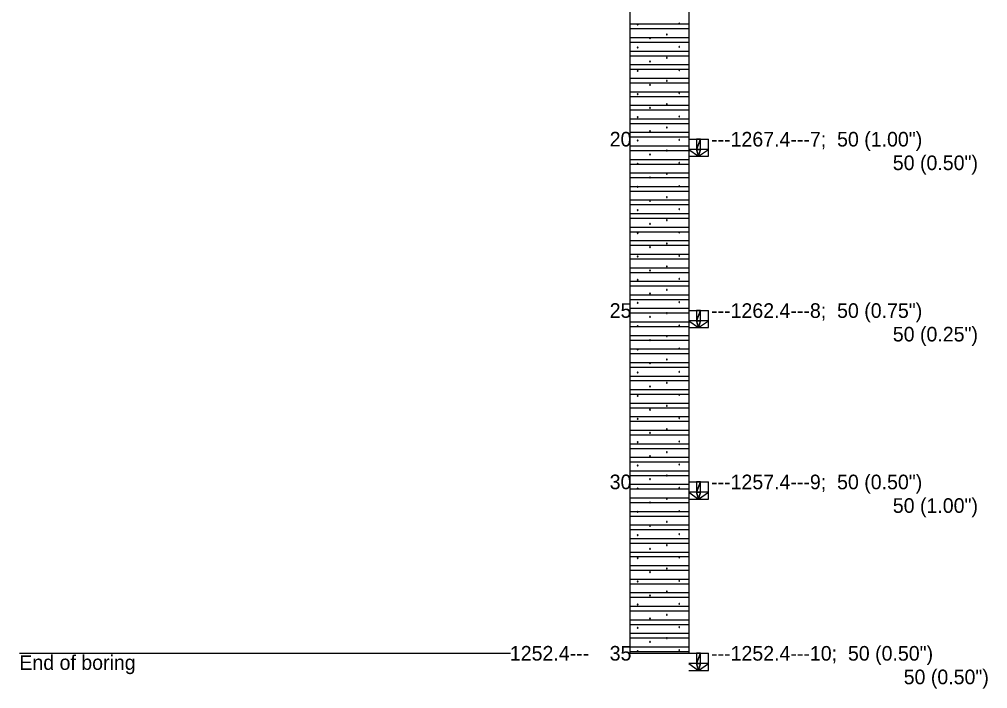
# Model space of a CAD drawing. Extents: x -6 to 173, y 24 to 64.
# Drawn here: x 54.91 to 63.13, y 39.25 to 44.93 of the extents above; entities that cross this region are included whole.
import ezdxf

# ---------------------------------------------------------------- set-up
doc = ezdxf.new("R2010")
doc.units = 0

msp = doc.modelspace()

# ---------------------------------------------------------------- linework, layer by layer
for points in [[(60.0894, 49.7271), (60.0894, 39.5527)], [(60.5894, 49.7271), (60.5894, 39.5527)], [(60.0894, 44.8898), (60.5894, 44.8898)], [(60.1598, 44.8862), (60.1581, 44.889), (60.1548, 44.889), (60.1532, 44.8862), (60.1548, 44.8833), (60.1581, 44.8833), (60.1598, 44.8862)], [(60.5125, 44.8927), (60.5109, 44.8956), (60.5076, 44.8956), (60.506, 44.8927), (60.5076, 44.8899), (60.5109, 44.8899), (60.5125, 44.8927)], [(60.0894, 44.8504), (60.5894, 44.8504)], [(60.0894, 44.7749), (60.5894, 44.7749)], [(60.407, 44.8002), (60.4054, 44.803), (60.4021, 44.803), (60.4004, 44.8002), (60.4021, 44.7974), (60.4054, 44.7974), (60.407, 44.8002)], [(60.0894, 44.7356), (60.5894, 44.7356)], [(60.1598, 44.6894), (60.1581, 44.6922), (60.1548, 44.6922), (60.1532, 44.6894), (60.1548, 44.6865), (60.1581, 44.6865), (60.1598, 44.6894)], [(60.2644, 44.7683), (60.2628, 44.7712), (60.2595, 44.7712), (60.2579, 44.7684), (60.2595, 44.7655), (60.2628, 44.7655), (60.2644, 44.7683)], [(60.5125, 44.6959), (60.5109, 44.6987), (60.5076, 44.6987), (60.506, 44.6959), (60.5076, 44.693), (60.5109, 44.693), (60.5125, 44.6959)], [(60.0894, 44.6601), (60.5894, 44.6601)], [(60.0894, 44.6207), (60.5894, 44.6207)], [(60.0894, 44.5453), (60.5894, 44.5453)], [(60.2644, 44.5714), (60.2628, 44.5743), (60.2595, 44.5743), (60.2579, 44.5715), (60.2595, 44.5686), (60.2628, 44.5686), (60.2644, 44.5714)], [(60.407, 44.6033), (60.4054, 44.6062), (60.4021, 44.6062), (60.4004, 44.6033), (60.4021, 44.6005), (60.4054, 44.6005), (60.407, 44.6033)], [(60.0894, 44.5059), (60.5894, 44.5059)], [(60.1598, 44.4925), (60.1581, 44.4953), (60.1548, 44.4953), (60.1532, 44.4925), (60.1548, 44.4896), (60.1581, 44.4896), (60.1598, 44.4925)], [(60.5125, 44.499), (60.5109, 44.5019), (60.5076, 44.5019), (60.506, 44.499), (60.5076, 44.4962), (60.5109, 44.4962), (60.5125, 44.499)], [(60.0894, 44.4304), (60.5894, 44.4304)], [(60.0894, 44.3911), (60.5894, 44.3911)], [(60.2644, 44.3746), (60.2628, 44.3775), (60.2595, 44.3775), (60.2579, 44.3747), (60.2595, 44.3718), (60.2628, 44.3718), (60.2644, 44.3746)], [(60.407, 44.4065), (60.4054, 44.4093), (60.4021, 44.4093), (60.4004, 44.4065), (60.4021, 44.4037), (60.4054, 44.4037), (60.407, 44.4065)], [(60.0894, 44.3156), (60.5894, 44.3156)], [(60.1598, 44.2957), (60.1581, 44.2985), (60.1548, 44.2985), (60.1532, 44.2957), (60.1548, 44.2928), (60.1581, 44.2928), (60.1598, 44.2957)], [(60.5125, 44.3022), (60.5109, 44.305), (60.5076, 44.305), (60.506, 44.3022), (60.5076, 44.2993), (60.5109, 44.2993), (60.5125, 44.3022)], [(60.0894, 44.2762), (60.5894, 44.2762)], [(60.0894, 44.2008), (60.5894, 44.2008)], [(60.407, 44.2096), (60.4054, 44.2125), (60.4021, 44.2125), (60.4004, 44.2096), (60.4021, 44.2068), (60.4054, 44.2068), (60.407, 44.2096)], [(60.0894, 44.1614), (60.5894, 44.1614)], [(60.2644, 44.1777), (60.2628, 44.1806), (60.2595, 44.1806), (60.2579, 44.1778), (60.2595, 44.1749), (60.2628, 44.1749), (60.2644, 44.1777)], [(60.0894, 44.0859), (60.5894, 44.0859)], [(60.0894, 44.0466), (60.5894, 44.0466)], [(60.1598, 44.0988), (60.1581, 44.1016), (60.1548, 44.1016), (60.1532, 44.0988), (60.1548, 44.0959), (60.1581, 44.0959), (60.1598, 44.0988)], [(60.5125, 44.1053), (60.5109, 44.1082), (60.5076, 44.1082), (60.506, 44.1053), (60.5076, 44.1025), (60.5109, 44.1025), (60.5125, 44.1053)], [(60.0894, 43.9711), (60.5894, 43.9711)], [(60.2644, 43.9809), (60.2628, 43.9838), (60.2595, 43.9838), (60.2579, 43.981), (60.2595, 43.9781), (60.2628, 43.9781), (60.2644, 43.9809)], [(60.407, 44.0128), (60.4054, 44.0156), (60.4021, 44.0156), (60.4004, 44.0128), (60.4021, 44.01), (60.4054, 44.01), (60.407, 44.0128)], [(60.0894, 43.9317), (60.5894, 43.9317)], [(60.1598, 43.902), (60.1581, 43.9048), (60.1548, 43.9048), (60.1532, 43.902), (60.1548, 43.8991), (60.1581, 43.8991), (60.1598, 43.902)], [(60.5125, 43.9085), (60.5109, 43.9113), (60.5076, 43.9113), (60.506, 43.9085), (60.5076, 43.9056), (60.5109, 43.9056), (60.5125, 43.9085)], [(60.5894, 43.9131), (60.756, 43.9131)], [(60.756, 43.7678), (60.756, 43.9131)], [(60.0894, 43.8563), (60.5894, 43.8563)], [(60.0894, 43.8169), (60.5894, 43.8169)], [(60.407, 43.8159), (60.4054, 43.8188), (60.4021, 43.8188), (60.4004, 43.8159), (60.4021, 43.8131), (60.4054, 43.8131), (60.407, 43.8159)], [(60.0894, 43.7415), (60.5894, 43.7415)], [(60.1598, 43.7051), (60.1581, 43.7079), (60.1548, 43.7079), (60.1532, 43.7051), (60.1548, 43.7022), (60.1581, 43.7022), (60.1598, 43.7051)], [(60.2644, 43.784), (60.2628, 43.7869), (60.2595, 43.7869), (60.2579, 43.7841), (60.2595, 43.7812), (60.2628, 43.7812), (60.2644, 43.784)], [(60.5125, 43.7116), (60.5109, 43.7145), (60.5076, 43.7145), (60.506, 43.7116), (60.5076, 43.7088), (60.5109, 43.7088), (60.5125, 43.7116)], [(60.5894, 43.7678), (60.756, 43.7678)], [(60.0894, 43.7021), (60.5894, 43.7021)], [(60.0894, 43.6266), (60.5894, 43.6266)], [(60.0894, 43.5873), (60.5894, 43.5873)], [(60.2644, 43.5872), (60.2628, 43.5901), (60.2595, 43.5901), (60.2579, 43.5873), (60.2595, 43.5844), (60.2628, 43.5844), (60.2644, 43.5872)], [(60.407, 43.6191), (60.4054, 43.6219), (60.4021, 43.6219), (60.4004, 43.6191), (60.4021, 43.6163), (60.4054, 43.6163), (60.407, 43.6191)], [(60.0894, 43.5118), (60.5894, 43.5118)], [(60.0894, 43.4724), (60.5894, 43.4724)], [(60.1598, 43.5083), (60.1581, 43.5111), (60.1548, 43.5111), (60.1532, 43.5083), (60.1548, 43.5054), (60.1581, 43.5054), (60.1598, 43.5083)], [(60.5125, 43.5148), (60.5109, 43.5176), (60.5076, 43.5176), (60.506, 43.5148), (60.5076, 43.5119), (60.5109, 43.5119), (60.5125, 43.5148)], [(60.0894, 43.397), (60.5894, 43.397)], [(60.2644, 43.3903), (60.2628, 43.3932), (60.2595, 43.3932), (60.2579, 43.3904), (60.2595, 43.3875), (60.2628, 43.3875), (60.2644, 43.3903)], [(60.407, 43.4222), (60.4054, 43.4251), (60.4021, 43.4251), (60.4004, 43.4222), (60.4021, 43.4194), (60.4054, 43.4194), (60.407, 43.4222)], [(60.0894, 43.3576), (60.5894, 43.3576)], [(60.1598, 43.3114), (60.1581, 43.3142), (60.1548, 43.3142), (60.1532, 43.3114), (60.1548, 43.3085), (60.1581, 43.3085), (60.1598, 43.3114)], [(60.5125, 43.3179), (60.5109, 43.3208), (60.5076, 43.3208), (60.506, 43.3179), (60.5076, 43.3151), (60.5109, 43.3151), (60.5125, 43.3179)], [(60.0894, 43.2821), (60.5894, 43.2821)], [(60.0894, 43.2428), (60.5894, 43.2428)], [(60.407, 43.2254), (60.4054, 43.2282), (60.4021, 43.2282), (60.4004, 43.2254), (60.4021, 43.2226), (60.4054, 43.2226), (60.407, 43.2254)], [(60.0894, 43.1673), (60.5894, 43.1673)], [(60.2644, 43.1935), (60.2628, 43.1964), (60.2595, 43.1964), (60.2579, 43.1936), (60.2595, 43.1907), (60.2628, 43.1907), (60.2644, 43.1935)], [(60.0894, 43.1279), (60.5894, 43.1279)], [(60.0894, 43.0525), (60.5894, 43.0525)], [(60.1598, 43.1146), (60.1581, 43.1174), (60.1548, 43.1174), (60.1532, 43.1146), (60.1548, 43.1117), (60.1581, 43.1117), (60.1598, 43.1146)], [(60.5125, 43.121), (60.5109, 43.1239), (60.5076, 43.1239), (60.506, 43.121), (60.5076, 43.1182), (60.5109, 43.1182), (60.5125, 43.121)], [(60.0894, 43.0131), (60.5894, 43.0131)], [(60.2644, 42.9966), (60.2628, 42.9995), (60.2595, 42.9995), (60.2579, 42.9967), (60.2595, 42.9938), (60.2628, 42.9938), (60.2644, 42.9966)], [(60.407, 43.0285), (60.4054, 43.0314), (60.4021, 43.0314), (60.4004, 43.0285), (60.4021, 43.0257), (60.4054, 43.0257), (60.407, 43.0285)], [(60.0894, 42.9377), (60.5894, 42.9377)], [(60.0894, 42.8983), (60.5894, 42.8983)], [(60.1598, 42.9177), (60.1581, 42.9205), (60.1548, 42.9205), (60.1532, 42.9177), (60.1548, 42.9148), (60.1581, 42.9148), (60.1598, 42.9177)], [(60.5125, 42.9242), (60.5109, 42.9271), (60.5076, 42.9271), (60.506, 42.9242), (60.5076, 42.9214), (60.5109, 42.9214), (60.5125, 42.9242)], [(60.0894, 42.8228), (60.5894, 42.8228)], [(60.2644, 42.7998), (60.2628, 42.8027), (60.2595, 42.8027), (60.2579, 42.7999), (60.2595, 42.797), (60.2628, 42.797), (60.2644, 42.7998)], [(60.407, 42.8317), (60.4054, 42.8345), (60.4021, 42.8345), (60.4004, 42.8317), (60.4021, 42.8289), (60.4054, 42.8289), (60.407, 42.8317)], [(60.0894, 42.7835), (60.5894, 42.7835)], [(60.1598, 42.7209), (60.1581, 42.7237), (60.1548, 42.7237), (60.1532, 42.7209), (60.1548, 42.718), (60.1581, 42.718), (60.1598, 42.7209)], [(60.5125, 42.7273), (60.5109, 42.7302), (60.5076, 42.7302), (60.506, 42.7273), (60.5076, 42.7245), (60.5109, 42.7245), (60.5125, 42.7273)], [(60.0894, 42.708), (60.5894, 42.708)], [(60.0894, 42.6686), (60.5894, 42.6686)], [(60.407, 42.6348), (60.4054, 42.6377), (60.4021, 42.6377), (60.4004, 42.6348), (60.4021, 42.632), (60.4054, 42.632), (60.407, 42.6348)], [(60.0894, 42.5932), (60.5894, 42.5932)], [(60.2644, 42.6029), (60.2628, 42.6058), (60.2595, 42.6058), (60.2579, 42.603), (60.2595, 42.6001), (60.2628, 42.6001), (60.2644, 42.6029)], [(60.0894, 42.5538), (60.5894, 42.5538)], [(60.0894, 42.4783), (60.5894, 42.4783)], [(60.1598, 42.524), (60.1581, 42.5268), (60.1548, 42.5268), (60.1532, 42.524), (60.1548, 42.5211), (60.1581, 42.5211), (60.1598, 42.524)], [(60.5125, 42.5305), (60.5109, 42.5334), (60.5076, 42.5334), (60.506, 42.5305), (60.5076, 42.5277), (60.5109, 42.5277), (60.5125, 42.5305)], [(60.0894, 42.439), (60.5894, 42.439)], [(60.2644, 42.4061), (60.2628, 42.409), (60.2595, 42.409), (60.2579, 42.4062), (60.2595, 42.4033), (60.2628, 42.4033), (60.2644, 42.4061)], [(60.407, 42.438), (60.4054, 42.4408), (60.4021, 42.4408), (60.4004, 42.438), (60.4021, 42.4352), (60.4054, 42.4352), (60.407, 42.438)], [(60.5894, 42.4596), (60.756, 42.4596)], [(60.756, 42.3143), (60.756, 42.4596)], [(60.0894, 42.3635), (60.5894, 42.3635)], [(60.0894, 42.3241), (60.5894, 42.3241)], [(60.1598, 42.3272), (60.1581, 42.33), (60.1548, 42.33), (60.1532, 42.3272), (60.1548, 42.3243), (60.1581, 42.3243), (60.1598, 42.3272)], [(60.5125, 42.3336), (60.5109, 42.3365), (60.5076, 42.3365), (60.506, 42.3336), (60.5076, 42.3308), (60.5109, 42.3308), (60.5125, 42.3336)], [(60.5894, 42.3143), (60.756, 42.3143)], [(60.0894, 42.2487), (60.5894, 42.2487)], [(60.407, 42.2411), (60.4054, 42.2439), (60.4021, 42.2439), (60.4004, 42.2411), (60.4021, 42.2383), (60.4054, 42.2383), (60.407, 42.2411)], [(60.0894, 42.2093), (60.5894, 42.2093)], [(60.2644, 42.2092), (60.2628, 42.2121), (60.2595, 42.2121), (60.2579, 42.2093), (60.2595, 42.2064), (60.2628, 42.2064), (60.2644, 42.2092)], [(60.0894, 42.1338), (60.5894, 42.1338)], [(60.0894, 42.0945), (60.5894, 42.0945)], [(60.1598, 42.1303), (60.1581, 42.1331), (60.1548, 42.1331), (60.1532, 42.1303), (60.1548, 42.1274), (60.1581, 42.1274), (60.1598, 42.1303)], [(60.5125, 42.1368), (60.5109, 42.1397), (60.5076, 42.1397), (60.506, 42.1368), (60.5076, 42.134), (60.5109, 42.134), (60.5125, 42.1368)], [(60.0894, 42.019), (60.5894, 42.019)], [(60.2644, 42.0124), (60.2628, 42.0153), (60.2595, 42.0153), (60.2579, 42.0125), (60.2595, 42.0096), (60.2628, 42.0096), (60.2644, 42.0124)], [(60.407, 42.0443), (60.4054, 42.0471), (60.4021, 42.0471), (60.4004, 42.0443), (60.4021, 42.0415), (60.4054, 42.0415), (60.407, 42.0443)], [(60.0894, 41.9796), (60.5894, 41.9796)], [(60.0894, 41.9042), (60.5894, 41.9042)], [(60.1598, 41.9335), (60.1581, 41.9363), (60.1548, 41.9363), (60.1532, 41.9335), (60.1548, 41.9306), (60.1581, 41.9306), (60.1598, 41.9335)], [(60.5125, 41.9399), (60.5109, 41.9428), (60.5076, 41.9428), (60.506, 41.9399), (60.5076, 41.9371), (60.5109, 41.9371), (60.5125, 41.9399)], [(60.0894, 41.8648), (60.5894, 41.8648)], [(60.2644, 41.8155), (60.2628, 41.8184), (60.2595, 41.8184), (60.2579, 41.8156), (60.2595, 41.8127), (60.2628, 41.8127), (60.2644, 41.8155)], [(60.407, 41.8474), (60.4054, 41.8502), (60.4021, 41.8502), (60.4004, 41.8474), (60.4021, 41.8446), (60.4054, 41.8446), (60.407, 41.8474)], [(60.0894, 41.7894), (60.5894, 41.7894)], [(60.0894, 41.75), (60.5894, 41.75)], [(60.1598, 41.7366), (60.1581, 41.7394), (60.1548, 41.7394), (60.1532, 41.7366), (60.1548, 41.7337), (60.1581, 41.7337), (60.1598, 41.7366)], [(60.5125, 41.7431), (60.5109, 41.746), (60.5076, 41.746), (60.506, 41.7431), (60.5076, 41.7403), (60.5109, 41.7403), (60.5125, 41.7431)], [(60.0894, 41.6745), (60.5894, 41.6745)], [(60.407, 41.6506), (60.4054, 41.6534), (60.4021, 41.6534), (60.4004, 41.6506), (60.4021, 41.6478), (60.4054, 41.6478), (60.407, 41.6506)], [(60.0894, 41.6352), (60.5894, 41.6352)], [(60.2644, 41.6187), (60.2628, 41.6216), (60.2595, 41.6216), (60.2579, 41.6188), (60.2595, 41.6159), (60.2628, 41.6159), (60.2644, 41.6187)], [(60.0894, 41.5597), (60.5894, 41.5597)], [(60.0894, 41.5203), (60.5894, 41.5203)], [(60.1598, 41.5398), (60.1581, 41.5426), (60.1548, 41.5426), (60.1532, 41.5398), (60.1548, 41.5369), (60.1581, 41.5369), (60.1598, 41.5398)], [(60.5125, 41.5462), (60.5109, 41.5491), (60.5076, 41.5491), (60.506, 41.5462), (60.5076, 41.5434), (60.5109, 41.5434), (60.5125, 41.5462)], [(60.0894, 41.4449), (60.5894, 41.4449)], [(60.0894, 41.4055), (60.5894, 41.4055)], [(60.2644, 41.4218), (60.2628, 41.4247), (60.2595, 41.4247), (60.2579, 41.4219), (60.2595, 41.419), (60.2628, 41.419), (60.2644, 41.4218)], [(60.407, 41.4537), (60.4054, 41.4565), (60.4021, 41.4565), (60.4004, 41.4537), (60.4021, 41.4509), (60.4054, 41.4509), (60.407, 41.4537)], [(60.0894, 41.33), (60.5894, 41.33)], [(60.1598, 41.3429), (60.1581, 41.3457), (60.1548, 41.3457), (60.1532, 41.3429), (60.1548, 41.34), (60.1581, 41.34), (60.1598, 41.3429)], [(60.5125, 41.3494), (60.5109, 41.3523), (60.5076, 41.3523), (60.506, 41.3494), (60.5076, 41.3466), (60.5109, 41.3466), (60.5125, 41.3494)], [(60.0894, 41.2907), (60.5894, 41.2907)], [(60.407, 41.2569), (60.4054, 41.2597), (60.4021, 41.2597), (60.4004, 41.2569), (60.4021, 41.2541), (60.4054, 41.2541), (60.407, 41.2569)], [(60.0894, 41.2152), (60.5894, 41.2152)], [(60.0894, 41.1758), (60.5894, 41.1758)], [(60.2644, 41.225), (60.2628, 41.2279), (60.2595, 41.2279), (60.2579, 41.2251), (60.2595, 41.2222), (60.2628, 41.2222), (60.2644, 41.225)], [(60.0894, 41.1004), (60.5894, 41.1004)], [(60.1598, 41.146), (60.1581, 41.1489), (60.1548, 41.1489), (60.1532, 41.146), (60.1548, 41.1432), (60.1581, 41.1432), (60.1598, 41.146)], [(60.5125, 41.1525), (60.5109, 41.1554), (60.5076, 41.1554), (60.506, 41.1525), (60.5076, 41.1497), (60.5109, 41.1497), (60.5125, 41.1525)], [(60.0894, 41.061), (60.5894, 41.061)], [(60.2644, 41.0281), (60.2628, 41.031), (60.2595, 41.031), (60.2579, 41.0282), (60.2595, 41.0253), (60.2628, 41.0253), (60.2644, 41.0281)], [(60.407, 41.06), (60.4054, 41.0628), (60.4021, 41.0628), (60.4004, 41.06), (60.4021, 41.0572), (60.4054, 41.0572), (60.407, 41.06)], [(60.5894, 41.0062), (60.756, 41.0062)], [(60.756, 40.8608), (60.756, 41.0062)], [(60.0894, 40.9856), (60.5894, 40.9856)], [(60.0894, 40.9462), (60.5894, 40.9462)], [(60.1598, 40.9492), (60.1581, 40.952), (60.1548, 40.952), (60.1532, 40.9492), (60.1548, 40.9463), (60.1581, 40.9463), (60.1598, 40.9492)], [(60.5125, 40.9557), (60.5109, 40.9586), (60.5076, 40.9586), (60.506, 40.9557), (60.5076, 40.9529), (60.5109, 40.9529), (60.5125, 40.9557)], [(60.0894, 40.8707), (60.5894, 40.8707)], [(60.0894, 40.8314), (60.5894, 40.8314)], [(60.2644, 40.8313), (60.2628, 40.8342), (60.2595, 40.8342), (60.2579, 40.8314), (60.2595, 40.8285), (60.2628, 40.8285), (60.2644, 40.8313)], [(60.407, 40.8632), (60.4054, 40.866), (60.4021, 40.866), (60.4004, 40.8632), (60.4021, 40.8604), (60.4054, 40.8604), (60.407, 40.8632)], [(60.5894, 40.8608), (60.756, 40.8608)], [(60.0894, 40.7559), (60.5894, 40.7559)], [(60.1598, 40.7523), (60.1581, 40.7552), (60.1548, 40.7552), (60.1532, 40.7523), (60.1548, 40.7495), (60.1581, 40.7495), (60.1598, 40.7523)], [(60.5125, 40.7588), (60.5109, 40.7617), (60.5076, 40.7617), (60.506, 40.7588), (60.5076, 40.756), (60.5109, 40.756), (60.5125, 40.7588)], [(60.0894, 40.7165), (60.5894, 40.7165)], [(60.407, 40.6663), (60.4054, 40.6691), (60.4021, 40.6691), (60.4004, 40.6663), (60.4021, 40.6635), (60.4054, 40.6635), (60.407, 40.6663)], [(60.0894, 40.6411), (60.5894, 40.6411)], [(60.0894, 40.6017), (60.5894, 40.6017)], [(60.2644, 40.6344), (60.2628, 40.6373), (60.2595, 40.6373), (60.2579, 40.6345), (60.2595, 40.6316), (60.2628, 40.6316), (60.2644, 40.6344)], [(60.0894, 40.5262), (60.5894, 40.5262)], [(60.1598, 40.5555), (60.1581, 40.5583), (60.1548, 40.5583), (60.1532, 40.5555), (60.1548, 40.5526), (60.1581, 40.5526), (60.1598, 40.5555)], [(60.5125, 40.562), (60.5109, 40.5649), (60.5076, 40.5649), (60.506, 40.562), (60.5076, 40.5592), (60.5109, 40.5592), (60.5125, 40.562)], [(60.0894, 40.4869), (60.5894, 40.4869)], [(60.2644, 40.4376), (60.2628, 40.4405), (60.2595, 40.4405), (60.2579, 40.4377), (60.2595, 40.4348), (60.2628, 40.4348), (60.2644, 40.4376)], [(60.407, 40.4695), (60.4054, 40.4723), (60.4021, 40.4723), (60.4004, 40.4695), (60.4021, 40.4667), (60.4054, 40.4667), (60.407, 40.4695)], [(60.0894, 40.4114), (60.5894, 40.4114)], [(60.0894, 40.372), (60.5894, 40.372)], [(60.1598, 40.3586), (60.1581, 40.3615), (60.1548, 40.3615), (60.1532, 40.3586), (60.1548, 40.3558), (60.1581, 40.3558), (60.1598, 40.3586)], [(60.5125, 40.3651), (60.5109, 40.368), (60.5076, 40.368), (60.506, 40.3651), (60.5076, 40.3623), (60.5109, 40.3623), (60.5125, 40.3651)], [(60.0894, 40.2966), (60.5894, 40.2966)], [(60.0894, 40.2572), (60.5894, 40.2572)], [(60.407, 40.2726), (60.4054, 40.2754), (60.4021, 40.2754), (60.4004, 40.2726), (60.4021, 40.2698), (60.4054, 40.2698), (60.407, 40.2726)], [(60.0894, 40.1817), (60.5894, 40.1817)], [(60.2644, 40.2407), (60.2628, 40.2436), (60.2595, 40.2436), (60.2579, 40.2408), (60.2595, 40.2379), (60.2628, 40.2379), (60.2644, 40.2407)], [(60.0894, 40.1424), (60.5894, 40.1424)], [(60.1598, 40.1618), (60.1581, 40.1646), (60.1548, 40.1646), (60.1532, 40.1618), (60.1548, 40.1589), (60.1581, 40.1589), (60.1598, 40.1618)], [(60.5125, 40.1683), (60.5109, 40.1712), (60.5076, 40.1712), (60.506, 40.1683), (60.5076, 40.1655), (60.5109, 40.1655), (60.5125, 40.1683)], [(60.0894, 40.0669), (60.5894, 40.0669)], [(60.0894, 40.0275), (60.5894, 40.0275)], [(60.2644, 40.0439), (60.2628, 40.0468), (60.2595, 40.0468), (60.2579, 40.0439), (60.2595, 40.0411), (60.2628, 40.0411), (60.2644, 40.0439)], [(60.407, 40.0758), (60.4054, 40.0786), (60.4021, 40.0786), (60.4004, 40.0758), (60.4021, 40.073), (60.4054, 40.073), (60.407, 40.0758)], [(60.0894, 39.9521), (60.5894, 39.9521)], [(60.1598, 39.9649), (60.1581, 39.9678), (60.1548, 39.9678), (60.1532, 39.9649), (60.1548, 39.9621), (60.1581, 39.9621), (60.1598, 39.9649)], [(60.5125, 39.9714), (60.5109, 39.9743), (60.5076, 39.9743), (60.506, 39.9714), (60.5076, 39.9686), (60.5109, 39.9686), (60.5125, 39.9714)], [(60.0894, 39.9127), (60.5894, 39.9127)], [(60.2644, 39.847), (60.2628, 39.8499), (60.2595, 39.8499), (60.2579, 39.8471), (60.2595, 39.8442), (60.2628, 39.8442), (60.2644, 39.847)], [(60.407, 39.8789), (60.4054, 39.8817), (60.4021, 39.8817), (60.4004, 39.8789), (60.4021, 39.8761), (60.4054, 39.8761), (60.407, 39.8789)], [(60.0894, 39.8373), (60.5894, 39.8373)], [(60.0894, 39.7979), (60.5894, 39.7979)], [(60.1598, 39.7681), (60.1581, 39.7709), (60.1548, 39.7709), (60.1532, 39.7681), (60.1548, 39.7652), (60.1581, 39.7652), (60.1598, 39.7681)], [(60.5125, 39.7746), (60.5109, 39.7775), (60.5076, 39.7775), (60.506, 39.7746), (60.5076, 39.7718), (60.5109, 39.7718), (60.5125, 39.7746)], [(60.0894, 39.7224), (60.5894, 39.7224)], [(60.0894, 39.6831), (60.5894, 39.6831)], [(60.407, 39.6821), (60.4054, 39.6849), (60.4021, 39.6849), (60.4004, 39.6821), (60.4021, 39.6793), (60.4054, 39.6793), (60.407, 39.6821)], [(60.0894, 39.6076), (60.5894, 39.6076)], [(60.2644, 39.6502), (60.2628, 39.6531), (60.2595, 39.6531), (60.2579, 39.6502), (60.2595, 39.6474), (60.2628, 39.6474), (60.2644, 39.6502)], [(54.9103, 39.5527), (59.077, 39.5527)], [(60.0894, 39.5682), (60.5894, 39.5682)], [(60.0894, 39.5527), (60.5894, 39.5527)], [(60.1598, 39.5712), (60.1581, 39.5741), (60.1548, 39.5741), (60.1532, 39.5712), (60.1548, 39.5684), (60.1581, 39.5684), (60.1598, 39.5712)], [(60.5125, 39.5777), (60.5109, 39.5806), (60.5076, 39.5806), (60.506, 39.5777), (60.5076, 39.5749), (60.5109, 39.5749), (60.5125, 39.5777)], [(60.5894, 39.5527), (60.756, 39.5527)], [(60.756, 39.4073), (60.756, 39.5527)], [(60.5894, 39.4073), (60.756, 39.4073)]]:
    msp.add_lwpolyline(points)
for points in [[(60.656, 43.8259), (60.6894, 43.8259), (60.6894, 43.9131), (60.656, 43.8259)], [(60.656, 43.8259), (60.6894, 43.9131), (60.656, 43.9131), (60.656, 43.8259)], [(60.656, 43.8259), (60.5894, 43.8259), (60.6727, 43.7678), (60.656, 43.8259)], [(60.656, 43.8259), (60.6727, 43.7678), (60.6894, 43.8259), (60.656, 43.8259)], [(60.6727, 43.7678), (60.756, 43.8259), (60.6894, 43.8259), (60.6727, 43.7678)], [(60.656, 42.3724), (60.6894, 42.3724), (60.6894, 42.4596), (60.656, 42.3724)], [(60.656, 42.3724), (60.6894, 42.4596), (60.656, 42.4596), (60.656, 42.3724)], [(60.656, 42.3724), (60.5894, 42.3724), (60.6727, 42.3143), (60.656, 42.3724)], [(60.656, 42.3724), (60.6727, 42.3143), (60.6894, 42.3724), (60.656, 42.3724)], [(60.6727, 42.3143), (60.756, 42.3724), (60.6894, 42.3724), (60.6727, 42.3143)], [(60.656, 40.9189), (60.6894, 40.9189), (60.6894, 41.0062), (60.656, 40.9189)], [(60.656, 40.9189), (60.6894, 41.0062), (60.656, 41.0062), (60.656, 40.9189)], [(60.656, 40.9189), (60.5894, 40.9189), (60.6727, 40.8608), (60.656, 40.9189)], [(60.656, 40.9189), (60.6727, 40.8608), (60.6894, 40.9189), (60.656, 40.9189)], [(60.6727, 40.8608), (60.756, 40.9189), (60.6894, 40.9189), (60.6727, 40.8608)], [(60.656, 39.4655), (60.6894, 39.4655), (60.6894, 39.5527), (60.656, 39.4655)], [(60.656, 39.4655), (60.6894, 39.5527), (60.656, 39.5527), (60.656, 39.4655)], [(60.656, 39.4655), (60.5894, 39.4655), (60.6727, 39.4073), (60.656, 39.4655)], [(60.656, 39.4655), (60.6727, 39.4073), (60.6894, 39.4655), (60.656, 39.4655)], [(60.6727, 39.4073), (60.756, 39.4655), (60.6894, 39.4655), (60.6727, 39.4073)]]:
    msp.add_lwpolyline(points, close=True)

# ---------------------------------------------------------------- texts
for s, p in [('20', (59.9189, 43.8511)), ('---1267.4---7;  50 (1.00")', (60.7792, 43.8505)), ('50 (0.50")', (62.321, 43.6505)), ('25', (59.9189, 42.3976)), ('---1262.4---8;  50 (0.75")', (60.7792, 42.3971)), ('50 (0.25")', (62.321, 42.1971)), ('30', (59.9189, 40.9442)), ('---1257.4---9;  50 (0.50")', (60.7792, 40.9436)), ('50 (1.00")', (62.321, 40.7436)), ('1252.4---', (59.0721, 39.4907)), ('35', (59.9189, 39.4907)), ('---1252.4---10;  50 (0.50")', (60.7792, 39.4901)), ('End of boring', (54.9103, 39.412)), ('50 (0.50")', (62.4133, 39.2901))]:
    msp.add_text(s, height=0.124).set_placement(p)

doc.saveas('drawing.dxf')
